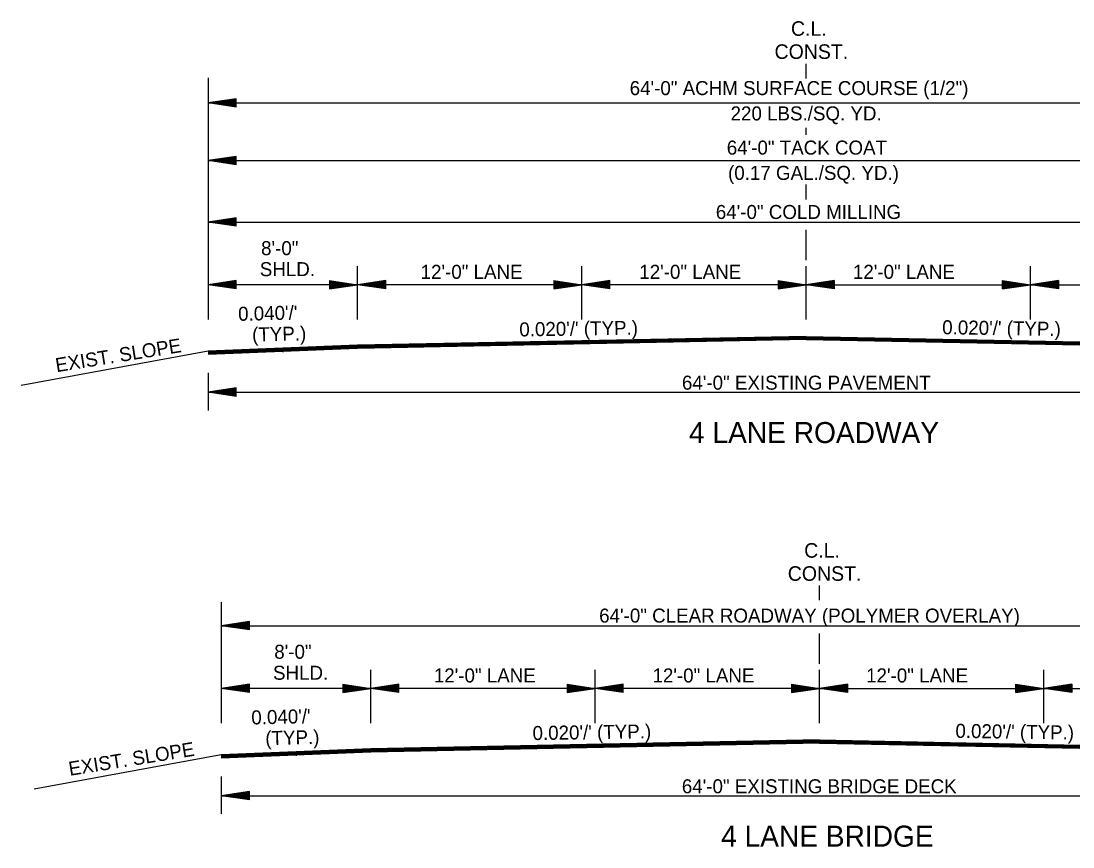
# Model space of a CAD drawing. Extents: x 544199 to 1930787, y -1968972 to 596640.
# Drawn here: x 546393 to 546956, y -1954285 to -1953843 of the extents above; entities that cross this region are included whole.
import ezdxf

# ---------------------------------------------------------------- set-up
doc = ezdxf.new("R2010")
doc.units = 0
doc.layers.add('R_Draft', color=7, linetype='Continuous')

msp = doc.modelspace()

# ---------------------------------------------------------------- linework, layer by layer
at = {"layer": 'R_Draft'}
for p, q in [((546813.23, -1953873.27), (546813.23, -1953865.42)), ((546493.23, -1953872.91), (546493.23, -1954002.37)), ((546508.23, -1953884.12), (546493.23, -1953886.37)), ((546493.23, -1953886.37), (547133.23, -1953886.37)), ((546508.23, -1953888.62), (546493.23, -1953886.37)), ((546508.23, -1953884.49), (546495.73, -1953886.37)), ((546508.23, -1953888.24), (546495.73, -1953886.37)), ((546508.23, -1953884.88), (546498.31, -1953886.37)), ((546508.23, -1953887.86), (546498.31, -1953886.37)), ((546508.23, -1953885.25), (546500.81, -1953886.37)), ((546508.23, -1953887.49), (546500.81, -1953886.37)), ((546508.23, -1953885.63), (546503.35, -1953886.37)), ((546508.23, -1953887.1), (546503.35, -1953886.37)), ((546508.23, -1953886.02), (546505.86, -1953886.37)), ((546508.23, -1953886.72), (546505.86, -1953886.37)), ((546508.23, -1953888.62), (546508.23, -1953884.12)), ((546813.23, -1953903.4), (546813.23, -1953899.72)), ((546508.23, -1953914.99), (546493.23, -1953917.24)), ((546493.23, -1953917.24), (547133.23, -1953917.24)), ((546508.23, -1953919.49), (546493.23, -1953917.24)), ((546508.23, -1953915.36), (546495.73, -1953917.24)), ((546508.23, -1953919.11), (546495.73, -1953917.24)), ((546508.23, -1953915.75), (546498.31, -1953917.24)), ((546508.23, -1953918.73), (546498.31, -1953917.24)), ((546508.23, -1953916.12), (546500.81, -1953917.24)), ((546508.23, -1953918.36), (546500.81, -1953917.24)), ((546508.23, -1953916.5), (546503.35, -1953917.24)), ((546508.23, -1953917.97), (546503.35, -1953917.24)), ((546508.23, -1953916.89), (546505.86, -1953917.24)), ((546508.23, -1953917.59), (546505.86, -1953917.24)), ((546508.23, -1953919.49), (546508.23, -1953914.99)), ((546813.23, -1953938.14), (546813.23, -1953930.08)), ((546508.23, -1953947.92), (546493.23, -1953950.17)), ((546493.23, -1953950.17), (547133.23, -1953950.17)), ((546508.23, -1953952.42), (546493.23, -1953950.17)), ((546508.23, -1953948.29), (546495.73, -1953950.17)), ((546508.23, -1953952.04), (546495.73, -1953950.17)), ((546508.23, -1953948.68), (546498.31, -1953950.17)), ((546508.23, -1953951.66), (546498.31, -1953950.17)), ((546508.23, -1953949.05), (546500.81, -1953950.17)), ((546508.23, -1953951.29), (546500.81, -1953950.17)), ((546508.23, -1953949.43), (546503.35, -1953950.17)), ((546508.23, -1953950.9), (546503.35, -1953950.17)), ((546508.23, -1953949.82), (546505.86, -1953950.17)), ((546508.23, -1953950.52), (546505.86, -1953950.17)), ((546508.23, -1953952.42), (546508.23, -1953947.92)), ((546813.23, -1953970.47), (546813.23, -1953954.3)), ((546573.23, -1954002.37), (546573.23, -1953973.81)), ((546693.23, -1954002.37), (546693.23, -1953973.81)), ((546813.23, -1954002.37), (546813.23, -1953973.81)), ((546813.23, -1954002.37), (546813.23, -1953973.81)), ((546933.23, -1954002.37), (546933.23, -1953973.81)), ((546508.23, -1953981.46), (546493.23, -1953983.71)), ((546593.23, -1953983.71), (546493.23, -1953983.71)), ((546508.23, -1953985.96), (546493.23, -1953983.71)), ((546508.23, -1953981.83), (546495.73, -1953983.71)), ((546508.23, -1953985.58), (546495.73, -1953983.71)), ((546508.23, -1953982.21), (546498.31, -1953983.71)), ((546508.23, -1953985.2), (546498.31, -1953983.71)), ((546508.23, -1953982.59), (546500.81, -1953983.71)), ((546508.23, -1953984.82), (546500.81, -1953983.71)), ((546508.23, -1953982.97), (546503.35, -1953983.71)), ((546508.23, -1953984.43), (546503.35, -1953983.71)), ((546508.23, -1953983.35), (546505.86, -1953983.71)), ((546508.23, -1953984.06), (546505.86, -1953983.71)), ((546508.23, -1953985.96), (546508.23, -1953981.46)), ((546558.23, -1953981.46), (546573.23, -1953983.71)), ((546558.23, -1953981.46), (546558.23, -1953985.96)), ((546558.23, -1953981.83), (546570.72, -1953983.71)), ((546558.23, -1953982.21), (546568.14, -1953983.71)), ((546558.23, -1953982.59), (546565.65, -1953983.71)), ((546558.23, -1953982.98), (546563.1, -1953983.71)), ((546558.23, -1953983.35), (546560.6, -1953983.71)), ((546558.23, -1953985.96), (546573.23, -1953983.71)), ((546558.23, -1953984.44), (546563.1, -1953983.71)), ((546558.23, -1953985.2), (546568.14, -1953983.71)), ((546558.23, -1953985.58), (546570.72, -1953983.71)), ((546558.23, -1953984.82), (546565.65, -1953983.71)), ((546558.23, -1953984.06), (546560.6, -1953983.71)), ((546588.23, -1953981.46), (546573.23, -1953983.71)), ((546588.23, -1953985.96), (546573.23, -1953983.71)), ((546588.23, -1953981.83), (546575.73, -1953983.71)), ((546588.23, -1953985.58), (546575.73, -1953983.71)), ((546588.23, -1953982.21), (546578.31, -1953983.71)), ((546588.23, -1953985.2), (546578.31, -1953983.71)), ((546588.23, -1953982.59), (546580.81, -1953983.71)), ((546588.23, -1953984.82), (546580.81, -1953983.71)), ((546588.23, -1953982.97), (546583.35, -1953983.71)), ((546588.23, -1953984.43), (546583.35, -1953983.71)), ((546588.23, -1953983.35), (546585.86, -1953983.71)), ((546588.23, -1953984.06), (546585.86, -1953983.71)), ((546588.23, -1953985.96), (546588.23, -1953981.46)), ((546703.23, -1953983.71), (546593.23, -1953983.71)), ((546678.23, -1953981.46), (546693.23, -1953983.71)), ((546678.23, -1953981.46), (546678.23, -1953985.96)), ((546678.23, -1953981.83), (546690.72, -1953983.71)), ((546678.23, -1953982.21), (546688.14, -1953983.71)), ((546678.23, -1953982.59), (546685.65, -1953983.71)), ((546678.23, -1953982.98), (546683.1, -1953983.71)), ((546678.23, -1953983.35), (546680.6, -1953983.71)), ((546678.23, -1953985.96), (546693.23, -1953983.71)), ((546678.23, -1953984.44), (546683.1, -1953983.71)), ((546678.23, -1953985.2), (546688.14, -1953983.71)), ((546678.23, -1953985.58), (546690.72, -1953983.71)), ((546678.23, -1953984.82), (546685.65, -1953983.71)), ((546678.23, -1953984.06), (546680.6, -1953983.71)), ((546708.23, -1953981.46), (546693.23, -1953983.71)), ((546708.23, -1953985.96), (546693.23, -1953983.71)), ((546708.23, -1953981.83), (546695.73, -1953983.71)), ((546708.23, -1953985.58), (546695.73, -1953983.71)), ((546708.23, -1953982.21), (546698.31, -1953983.71)), ((546708.23, -1953985.2), (546698.31, -1953983.71)), ((546708.23, -1953982.59), (546700.81, -1953983.71)), ((546708.23, -1953984.82), (546700.81, -1953983.71)), ((546813.23, -1953983.71), (546703.23, -1953983.71)), ((546708.23, -1953982.97), (546703.35, -1953983.71)), ((546708.23, -1953984.43), (546703.35, -1953983.71)), ((546708.23, -1953983.35), (546705.86, -1953983.71)), ((546708.23, -1953984.06), (546705.86, -1953983.71)), ((546708.23, -1953985.96), (546708.23, -1953981.46)), ((546798.23, -1953981.46), (546813.23, -1953983.71)), ((546798.23, -1953981.46), (546798.23, -1953985.96)), ((546798.23, -1953981.83), (546810.72, -1953983.71)), ((546798.23, -1953982.21), (546808.14, -1953983.71)), ((546798.23, -1953982.59), (546805.65, -1953983.71)), ((546798.23, -1953982.98), (546803.1, -1953983.71)), ((546798.23, -1953983.35), (546800.6, -1953983.71)), ((546798.23, -1953985.96), (546813.23, -1953983.71)), ((546798.23, -1953984.44), (546803.1, -1953983.71)), ((546798.23, -1953985.2), (546808.14, -1953983.71)), ((546798.23, -1953985.58), (546810.72, -1953983.71)), ((546798.23, -1953984.82), (546805.65, -1953983.71)), ((546798.23, -1953984.06), (546800.6, -1953983.71)), ((546828.23, -1953981.46), (546813.23, -1953983.71)), ((546813.23, -1953983.71), (546923.23, -1953983.71)), ((546828.23, -1953985.96), (546813.23, -1953983.71)), ((546828.23, -1953981.83), (546815.73, -1953983.71)), ((546828.23, -1953985.58), (546815.73, -1953983.71)), ((546828.23, -1953982.21), (546818.31, -1953983.71)), ((546828.23, -1953985.2), (546818.31, -1953983.71)), ((546828.23, -1953982.59), (546820.81, -1953983.71)), ((546828.23, -1953984.82), (546820.81, -1953983.71)), ((546828.23, -1953982.98), (546823.35, -1953983.71)), ((546828.23, -1953984.44), (546823.35, -1953983.71)), ((546828.23, -1953983.35), (546825.86, -1953983.71)), ((546828.23, -1953984.06), (546825.86, -1953983.71)), ((546828.23, -1953981.46), (546828.23, -1953985.96)), ((546918.23, -1953981.46), (546933.23, -1953983.71)), ((546918.23, -1953985.96), (546918.23, -1953981.46)), ((546918.23, -1953981.83), (546930.72, -1953983.71)), ((546918.23, -1953982.21), (546928.14, -1953983.71)), ((546918.23, -1953982.59), (546925.65, -1953983.71)), ((546918.23, -1953982.97), (546923.1, -1953983.71)), ((546918.23, -1953983.35), (546920.6, -1953983.71)), ((546918.23, -1953985.96), (546933.23, -1953983.71)), ((546918.23, -1953984.43), (546923.1, -1953983.71)), ((546918.23, -1953985.2), (546928.14, -1953983.71)), ((546918.23, -1953985.58), (546930.72, -1953983.71)), ((546918.23, -1953984.82), (546925.65, -1953983.71)), ((546918.23, -1953984.06), (546920.6, -1953983.71)), ((546923.23, -1953983.71), (547033.23, -1953983.71)), ((546948.23, -1953981.46), (546933.23, -1953983.71)), ((546948.23, -1953985.96), (546933.23, -1953983.71)), ((546948.23, -1953981.83), (546935.73, -1953983.71)), ((546948.23, -1953985.58), (546935.73, -1953983.71)), ((546948.23, -1953982.21), (546938.31, -1953983.71)), ((546948.23, -1953985.2), (546938.31, -1953983.71)), ((546948.23, -1953982.59), (546940.81, -1953983.71)), ((546948.23, -1953984.82), (546940.81, -1953983.71)), ((546948.23, -1953982.98), (546943.35, -1953983.71)), ((546948.23, -1953984.44), (546943.35, -1953983.71)), ((546948.23, -1953983.35), (546945.86, -1953983.71)), ((546948.23, -1953984.06), (546945.86, -1953983.71)), ((546948.23, -1953981.46), (546948.23, -1953985.96)), ((546813.23, -1954011.31), (546573.23, -1954016.11)), ((546813.24, -1954011.61), (546573.23, -1954016.41)), ((546813.24, -1954011.91), (546573.23, -1954016.71)), ((546813.25, -1954012.21), (546573.23, -1954017.01)), ((546813.25, -1954012.51), (546573.23, -1954017.31)), ((546813.26, -1954012.81), (546573.23, -1954017.61)), ((546813.2, -1954012.81), (547053.23, -1954017.61)), ((546813.21, -1954012.21), (547053.23, -1954017.01)), ((546813.21, -1954012.51), (547053.23, -1954017.31)), ((546813.22, -1954011.61), (547053.23, -1954016.41)), ((546813.22, -1954011.91), (547053.23, -1954016.71)), ((546813.23, -1954011.31), (547053.23, -1954016.11)), ((546573.23, -1954016.11), (546493.23, -1954019.31)), ((546573.23, -1954016.41), (546493.23, -1954019.61)), ((546573.23, -1954016.71), (546493.23, -1954019.91)), ((546573.23, -1954017.01), (546493.23, -1954020.21)), ((546573.23, -1954017.31), (546493.23, -1954020.51)), ((546573.23, -1954017.61), (546493.23, -1954020.81)), ((546573.23, -1954017.78), (546493.23, -1954020.98)), ((546533.23, -1954018.11), (546533.23, -1954019.78)), ((546813.26, -1954012.98), (546573.23, -1954017.78)), ((546813.2, -1954012.98), (547053.23, -1954017.78)), ((546493.23, -1954019.31), (546393.16, -1954037.69)), ((546493.23, -1954030.92), (546493.23, -1954050.92)), ((546508.23, -1954038.92), (546493.23, -1954041.17)), ((546508.23, -1954039.3), (546495.73, -1954041.17)), ((546508.23, -1954039.68), (546498.31, -1954041.17)), ((546508.23, -1954040.05), (546500.81, -1954041.17)), ((546508.23, -1954040.44), (546503.35, -1954041.17)), ((546508.23, -1954040.82), (546505.86, -1954041.17)), ((546508.23, -1954043.42), (546508.23, -1954038.92)), ((546508.23, -1954043.42), (546493.23, -1954041.17)), ((546493.23, -1954041.18), (547133.23, -1954041.25)), ((546508.23, -1954043.05), (546495.73, -1954041.17)), ((546508.23, -1954042.66), (546498.31, -1954041.17)), ((546508.23, -1954042.29), (546500.81, -1954041.17)), ((546508.23, -1954041.9), (546503.35, -1954041.17)), ((546508.23, -1954041.52), (546505.86, -1954041.17)), ((546820.3, -1954152.57), (546820.3, -1954144.71)), ((546500.3, -1954153.64), (546500.3, -1954218.37)), ((546515.3, -1954163.92), (546500.3, -1954166.17)), ((546515.3, -1954164.3), (546502.8, -1954166.17)), ((546515.3, -1954164.68), (546505.38, -1954166.17)), ((546515.3, -1954168.42), (546515.3, -1954163.92)), ((546500.3, -1954166.17), (547140.3, -1954166.17)), ((546515.3, -1954168.42), (546500.3, -1954166.17)), ((546515.3, -1954168.05), (546502.8, -1954166.17)), ((546515.3, -1954167.67), (546505.38, -1954166.17)), ((546515.3, -1954165.06), (546507.88, -1954166.17)), ((546515.3, -1954167.29), (546507.88, -1954166.17)), ((546515.3, -1954165.44), (546510.42, -1954166.17)), ((546515.3, -1954166.9), (546510.42, -1954166.17)), ((546515.3, -1954165.82), (546512.93, -1954166.17)), ((546515.3, -1954166.53), (546512.93, -1954166.17)), ((546820.3, -1954186.48), (546820.3, -1954170.31)), ((546580.3, -1954218.37), (546580.3, -1954189.82)), ((546700.3, -1954218.37), (546700.3, -1954189.82)), ((546820.3, -1954218.37), (546820.3, -1954189.82)), ((546820.3, -1954218.37), (546820.3, -1954189.82)), ((546940.3, -1954218.37), (546940.3, -1954189.82)), ((546515.3, -1954197.46), (546500.3, -1954199.71)), ((546515.3, -1954197.84), (546502.8, -1954199.71)), ((546515.3, -1954198.22), (546505.38, -1954199.71)), ((546515.3, -1954198.59), (546507.88, -1954199.71)), ((546515.3, -1954201.96), (546515.3, -1954197.46)), ((546565.3, -1954197.46), (546580.3, -1954199.71)), ((546565.3, -1954197.46), (546565.3, -1954201.96)), ((546565.3, -1954197.84), (546577.79, -1954199.71)), ((546565.3, -1954198.22), (546575.21, -1954199.71)), ((546565.3, -1954198.59), (546572.71, -1954199.71)), ((546595.3, -1954197.46), (546580.3, -1954199.71)), ((546595.3, -1954197.84), (546582.8, -1954199.71)), ((546595.3, -1954198.22), (546585.38, -1954199.71)), ((546595.3, -1954198.59), (546587.88, -1954199.71)), ((546595.3, -1954201.96), (546595.3, -1954197.46)), ((546685.3, -1954197.46), (546700.3, -1954199.71)), ((546685.3, -1954197.46), (546685.3, -1954201.96)), ((546685.3, -1954197.84), (546697.79, -1954199.71)), ((546685.3, -1954198.22), (546695.21, -1954199.71)), ((546685.3, -1954198.59), (546692.71, -1954199.71)), ((546715.3, -1954197.46), (546700.3, -1954199.71)), ((546715.3, -1954197.84), (546702.8, -1954199.71)), ((546715.3, -1954198.22), (546705.38, -1954199.71)), ((546715.3, -1954198.59), (546707.88, -1954199.71)), ((546715.3, -1954201.96), (546715.3, -1954197.46)), ((546805.3, -1954197.46), (546820.3, -1954199.71)), ((546805.3, -1954197.46), (546805.3, -1954201.96)), ((546805.3, -1954197.84), (546817.79, -1954199.71)), ((546805.3, -1954198.22), (546815.21, -1954199.71)), ((546805.3, -1954198.59), (546812.71, -1954199.71)), ((546835.3, -1954197.46), (546820.3, -1954199.71)), ((546835.3, -1954197.84), (546822.8, -1954199.71)), ((546835.3, -1954198.22), (546825.38, -1954199.71)), ((546835.3, -1954198.59), (546827.88, -1954199.71)), ((546835.3, -1954197.46), (546835.3, -1954201.96)), ((546925.3, -1954197.46), (546940.3, -1954199.71)), ((546925.3, -1954201.96), (546925.3, -1954197.46)), ((546925.3, -1954197.84), (546937.79, -1954199.71)), ((546925.3, -1954198.22), (546935.21, -1954199.71)), ((546925.3, -1954198.59), (546932.71, -1954199.71)), ((546955.3, -1954197.46), (546940.3, -1954199.71)), ((546955.3, -1954197.84), (546942.8, -1954199.71)), ((546955.3, -1954198.22), (546945.38, -1954199.71)), ((546955.3, -1954198.59), (546947.88, -1954199.71)), ((546955.3, -1954197.46), (546955.3, -1954201.96)), ((546600.3, -1954199.71), (546500.3, -1954199.71)), ((546515.3, -1954201.96), (546500.3, -1954199.71)), ((546515.3, -1954201.59), (546502.8, -1954199.71)), ((546515.3, -1954201.2), (546505.38, -1954199.71)), ((546515.3, -1954200.83), (546507.88, -1954199.71)), ((546515.3, -1954198.98), (546510.42, -1954199.71)), ((546515.3, -1954200.44), (546510.42, -1954199.71)), ((546515.3, -1954199.36), (546512.93, -1954199.71)), ((546515.3, -1954200.06), (546512.93, -1954199.71)), ((546565.3, -1954198.98), (546570.17, -1954199.71)), ((546565.3, -1954199.36), (546567.67, -1954199.71)), ((546565.3, -1954201.96), (546580.3, -1954199.71)), ((546565.3, -1954200.45), (546570.17, -1954199.71)), ((546565.3, -1954201.2), (546575.21, -1954199.71)), ((546565.3, -1954201.59), (546577.79, -1954199.71)), ((546565.3, -1954200.83), (546572.71, -1954199.71)), ((546565.3, -1954200.06), (546567.67, -1954199.71)), ((546595.3, -1954201.96), (546580.3, -1954199.71)), ((546595.3, -1954201.59), (546582.8, -1954199.71)), ((546595.3, -1954201.2), (546585.38, -1954199.71)), ((546595.3, -1954200.83), (546587.88, -1954199.71)), ((546595.3, -1954198.98), (546590.42, -1954199.71)), ((546595.3, -1954200.44), (546590.42, -1954199.71)), ((546595.3, -1954199.36), (546592.93, -1954199.71)), ((546595.3, -1954200.06), (546592.93, -1954199.71)), ((546710.3, -1954199.71), (546600.3, -1954199.71)), ((546685.3, -1954198.98), (546690.17, -1954199.71)), ((546685.3, -1954199.36), (546687.67, -1954199.71)), ((546685.3, -1954201.96), (546700.3, -1954199.71)), ((546685.3, -1954200.45), (546690.17, -1954199.71)), ((546685.3, -1954201.2), (546695.21, -1954199.71)), ((546685.3, -1954201.59), (546697.79, -1954199.71)), ((546685.3, -1954200.83), (546692.71, -1954199.71)), ((546685.3, -1954200.06), (546687.67, -1954199.71)), ((546715.3, -1954201.96), (546700.3, -1954199.71)), ((546715.3, -1954201.59), (546702.8, -1954199.71)), ((546715.3, -1954201.2), (546705.38, -1954199.71)), ((546715.3, -1954200.83), (546707.88, -1954199.71)), ((546820.3, -1954199.71), (546710.3, -1954199.71)), ((546715.3, -1954198.98), (546710.42, -1954199.71)), ((546715.3, -1954200.44), (546710.42, -1954199.71)), ((546715.3, -1954199.36), (546712.93, -1954199.71)), ((546715.3, -1954200.06), (546712.93, -1954199.71)), ((546805.3, -1954198.98), (546810.17, -1954199.71)), ((546805.3, -1954199.36), (546807.67, -1954199.71)), ((546805.3, -1954201.96), (546820.3, -1954199.71)), ((546805.3, -1954200.45), (546810.17, -1954199.71)), ((546805.3, -1954201.2), (546815.21, -1954199.71)), ((546805.3, -1954201.59), (546817.79, -1954199.71)), ((546805.3, -1954200.83), (546812.71, -1954199.71)), ((546805.3, -1954200.06), (546807.67, -1954199.71)), ((546820.3, -1954199.71), (546930.3, -1954199.71)), ((546835.3, -1954201.96), (546820.3, -1954199.71)), ((546835.3, -1954201.59), (546822.8, -1954199.71)), ((546835.3, -1954201.2), (546825.38, -1954199.71)), ((546835.3, -1954200.83), (546827.88, -1954199.71)), ((546835.3, -1954198.98), (546830.42, -1954199.71)), ((546835.3, -1954200.45), (546830.42, -1954199.71)), ((546835.3, -1954199.36), (546832.93, -1954199.71)), ((546835.3, -1954200.06), (546832.93, -1954199.71)), ((546925.3, -1954198.98), (546930.17, -1954199.71)), ((546925.3, -1954199.36), (546927.67, -1954199.71)), ((546925.3, -1954201.96), (546940.3, -1954199.71)), ((546925.3, -1954200.44), (546930.17, -1954199.71)), ((546925.3, -1954201.2), (546935.21, -1954199.71)), ((546925.3, -1954201.59), (546937.79, -1954199.71)), ((546925.3, -1954200.83), (546932.71, -1954199.71)), ((546925.3, -1954200.06), (546927.67, -1954199.71)), ((546930.3, -1954199.71), (547040.3, -1954199.71)), ((546955.3, -1954201.96), (546940.3, -1954199.71)), ((546955.3, -1954201.59), (546942.8, -1954199.71)), ((546955.3, -1954201.2), (546945.38, -1954199.71)), ((546955.3, -1954200.83), (546947.88, -1954199.71)), ((546955.3, -1954198.98), (546950.42, -1954199.71)), ((546955.3, -1954200.45), (546950.42, -1954199.71)), ((546955.3, -1954199.36), (546952.93, -1954199.71)), ((546955.3, -1954200.06), (546952.93, -1954199.71)), ((546580.3, -1954232.12), (546500.3, -1954235.32)), ((546580.3, -1954232.42), (546500.3, -1954235.62)), ((546820.3, -1954227.32), (546580.3, -1954232.12)), ((546820.3, -1954227.62), (546580.3, -1954232.42)), ((546820.31, -1954227.92), (546580.3, -1954232.72)), ((546820.31, -1954228.22), (546580.3, -1954233.02)), ((546820.32, -1954228.52), (546580.3, -1954233.32)), ((546820.33, -1954228.82), (546580.3, -1954233.62)), ((546820.33, -1954228.99), (546580.3, -1954233.79)), ((546820.26, -1954228.99), (547060.3, -1954233.79)), ((546820.27, -1954228.52), (547060.3, -1954233.32)), ((546820.27, -1954228.82), (547060.3, -1954233.62)), ((546820.28, -1954227.92), (547060.3, -1954232.72)), ((546820.28, -1954228.22), (547060.3, -1954233.02)), ((546820.29, -1954227.62), (547060.3, -1954232.42)), ((546820.3, -1954227.32), (547060.3, -1954232.12)), ((546500.3, -1954235.32), (546400.23, -1954253.69)), ((546580.3, -1954232.72), (546500.3, -1954235.92)), ((546580.3, -1954233.02), (546500.3, -1954236.22)), ((546580.3, -1954233.32), (546500.3, -1954236.52)), ((546580.3, -1954233.62), (546500.3, -1954236.82)), ((546580.3, -1954233.79), (546500.3, -1954236.99)), ((546540.3, -1954234.12), (546540.3, -1954235.79)), ((546500.3, -1954246.93), (546500.3, -1954266.93)), ((546515.3, -1954254.93), (546500.3, -1954257.18)), ((546515.3, -1954259.43), (546515.3, -1954254.93)), ((546500.3, -1954257.18), (547140.3, -1954257.26)), ((546515.3, -1954259.43), (546500.3, -1954257.18)), ((546515.3, -1954255.3), (546502.8, -1954257.18)), ((546515.3, -1954259.05), (546502.8, -1954257.18)), ((546515.3, -1954255.68), (546505.38, -1954257.18)), ((546515.3, -1954258.67), (546505.38, -1954257.18)), ((546515.3, -1954256.06), (546507.88, -1954257.18)), ((546515.3, -1954258.29), (546507.88, -1954257.18)), ((546515.3, -1954256.44), (546510.42, -1954257.18)), ((546515.3, -1954257.9), (546510.42, -1954257.18)), ((546515.3, -1954256.82), (546512.93, -1954257.18)), ((546515.3, -1954257.53), (546512.93, -1954257.18))]:
    msp.add_line(p, q, dxfattribs=at)

# ---------------------------------------------------------------- texts
for s, height, p in [('C.L.', 7.8, (546805.04, -1953850.48)), ('CONST.', 7.8, (546796.26, -1953862.84)), ('64\'-0" ACHM SURFACE COURSE (1/2")', 7.5, (546718.76, -1953882.2)), ('220 LBS./SQ. YD. ', 7.5, (546772.74, -1953895.75)), ('64\'-0" TACK COAT', 7.5, (546770.7, -1953914.04)), ('(0.17 GAL./SQ. YD.)', 7.5, (546771.38, -1953927.58)), ('64\'-0" COLD MILLING', 7.5, (546764.85, -1953948.5)), ('8\'-0" ', 7.5, (546521.57, -1953967.85)), ('SHLD.', 7.5, (546520.89, -1953979.1)), ('12\'-0" LANE', 7.5, (546606.93, -1953980.53)), ('12\'-0" LANE', 7.5, (546723.9, -1953980.53)), ('12\'-0" LANE', 7.5, (546838.19, -1953980.53)), ('64\'-0" EXISTING PAVEMENT', 7.5, (546746.72, -1954039.85)), ('4 LANE ROADWAY', 11.25, (546750.5, -1954068.41)), ('C.L.', 7.8, (546812.11, -1954129.77)), ('CONST.', 7.8, (546803.33, -1954142.14)), ('64\'-0" CLEAR ROADWAY (POLYMER OVERLAY)', 7.5, (546702.44, -1954164.5)), ('8\'-0" ', 7.5, (546528.63, -1954183.85)), ('SHLD.', 7.5, (546527.95, -1954195.1)), ('12\'-0" LANE', 7.5, (546613.99, -1954196.54)), ('12\'-0" LANE', 7.5, (546730.97, -1954196.54)), ('12\'-0" LANE', 7.5, (546845.25, -1954196.54)), ('64\'-0" EXISTING BRIDGE DECK', 7.5, (546746.67, -1954255.85)), ('4 LANE BRIDGE ', 11.25, (546767.67, -1954284.42))]:
    msp.add_text(s, height=height, dxfattribs=at).set_placement(p)
for s, rotation, p in [("0.040'/' ", 1.3184, (546509.38, -1954003.02)), ('(TYP.)', 1.3184, (546516.84, -1954014.1)), ("0.020'/' (TYP.)", 0.8719, (546659.78, -1954011.37)), ("0.020'/' (TYP.)", 359.1281, (546885.9, -1954010.15)), ('EXIST. SLOPE', 9.1534, (546412.18, -1954030.52)), ("0.040'/' ", 1.3184, (546516.44, -1954219.03)), ("0.020'/' (TYP.)", 0.8719, (546666.85, -1954227.38)), ("0.020'/' (TYP.)", 359.1281, (546892.96, -1954226.15)), ('(TYP.)', 1.3184, (546523.91, -1954230.11)), ('EXIST. SLOPE', 9.1534, (546419.25, -1954246.52))]:
    msp.add_text(s, height=7.5, rotation=rotation, dxfattribs=at).set_placement(p)

doc.saveas('drawing.dxf')
